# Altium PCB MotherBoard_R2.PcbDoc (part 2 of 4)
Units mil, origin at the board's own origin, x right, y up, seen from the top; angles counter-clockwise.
Board outline 9500 x 4600 mil, 4 copper layers (Top Layer, Power Layer, GND Layer, Bottom Layer), stack 61.6 mil thick; 206 components, 289 nets, 935 pads, 328 vias.
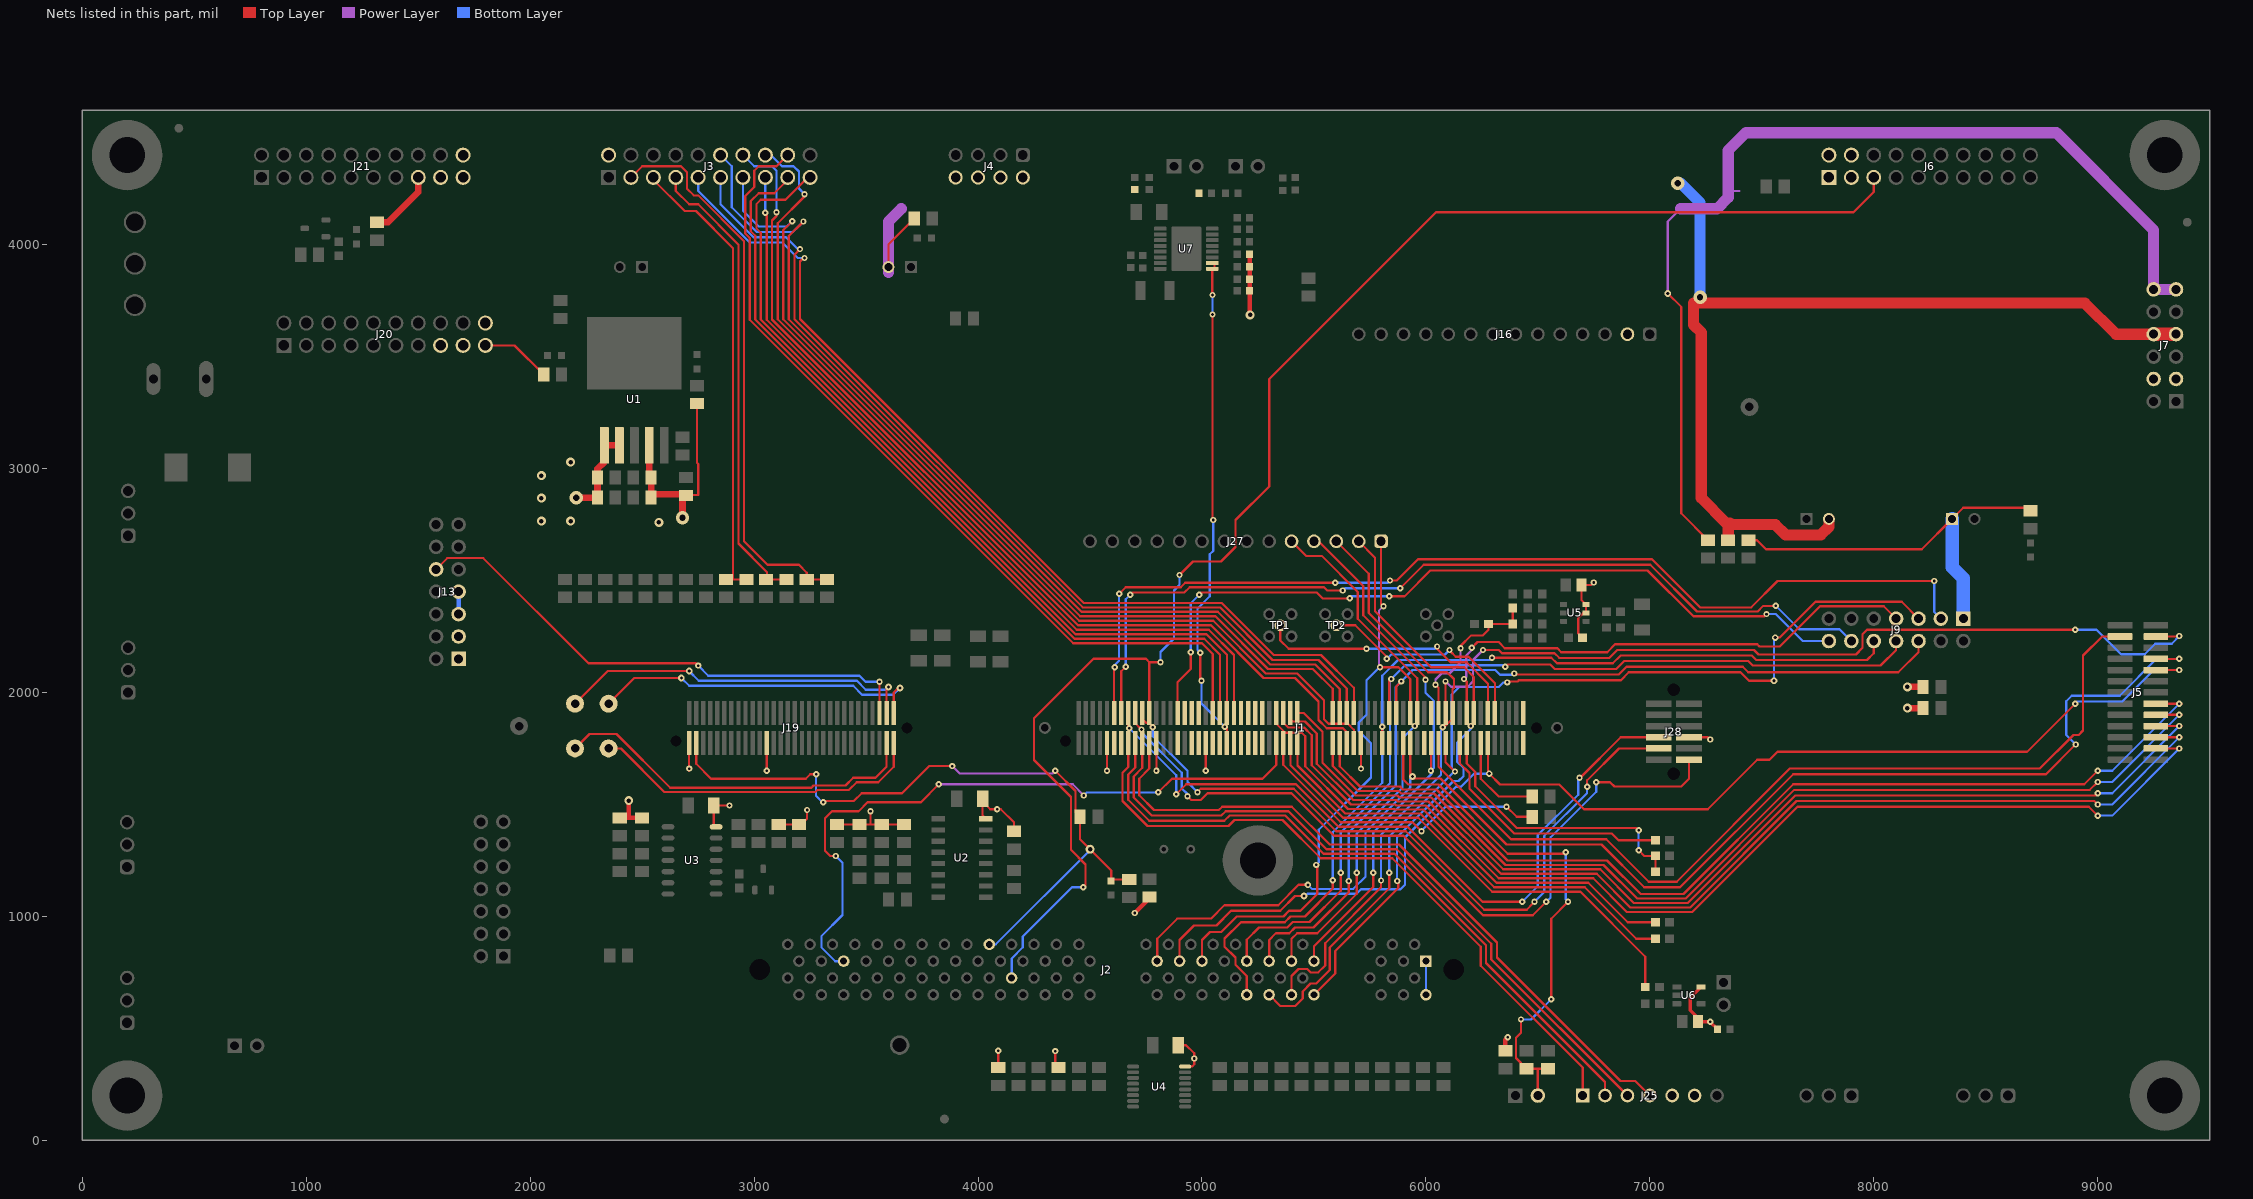
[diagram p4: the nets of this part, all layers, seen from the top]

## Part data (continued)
FID1 FID2 FID3: library part CMP-0077181-1, "Fiducial mark.  There is nothing to buy or mount.", Manufacturer=N/A
GP1 GP2 TP7 TP8 TP9 TP10: library part CMP-0078143-3, "TEST POINT.  No entry in BOM.", Manufacturer=N/A
H1 H2 H3 H4 H5: library part CMP-0003617-1, "Machine Screw, Round, #4-40 x 1/4, Nylon, Philips panhead", Manufacturer="B&F Fastener Supply", Supplier Part Number 1=H542-ND
J1: library part CMP-0003814-2, "C2000 controlCARD-120HSEC connector, SMT", Manufacturer=Samtec
J2: library part CMP-0075002-1, "Connector, DIM 1.27 mm 100 CKTS, An Identical Molex SD-87630-001  obsolete", Manufacturer="Texas Instruments"
J3 J6: library part CMP-0054719-2, "Header (Shrouded), 2.54mm, 10x2, Gold, TH", Color=Black, Current_A=3A, Manufacturer="Sullins Connector Solutions", Supplier Part Number 1=S9180-ND, Voltage_V=1kV
J4: library part CMP-0054803-2, "Header, 2.54mm, 4x2, Gold, R/A, TH", Color=Black, Current_A=3A, Manufacturer="Wurth Elektronik", Supplier Part Number 1=732-5353-ND, Voltage_V=250V
J5: library part CMP-0089180-1, Current_A=3.4A, Digikey Part Number=SAM9460-ND, Manufacturer=Samtec, Mouser Part Number=200-FTSH11301FDVK, Operating Temperature Range="-55°C to +125°C"
J7: library part CMP-0075412-2, "Header, 100mil, 6x2, Gold, TH", Color=Black, Current_A=6.3A, Manufacturer=Samtec, Supplier Part Number 1=SAM1028-06-ND, Voltage_V=550V
J8 J10 J12 J17 J23 J26: library part CMP-0054796-2, "Header, 2.54 mm, 3x1, Gold, TH", Color=Black, Manufacturer="Wurth Elektronik", Supplier Part Number 1=732-5316-ND
J9 J13 J22: library part CMP-0054695-2, "Header (shrouded), 100 mil, 7x2, Gold, TH", Manufacturer="Sullins Connector Solutions", Supplier Part Number 1=S9170-ND
J11 J15 J18 J24 J34: library part CMP-0054566-1, "Header, 100mil, 2x1, Gold, TH", Color=Black, Current_A=3A, Manufacturer="Sullins Connector Solutions", Supplier Part Number 1=S1011E-02-ND, Voltage_V=1.8kV
J14: library part CMP-0075114-1, "Power Jack, 2mm, R/A, TH", Color=Black, Manufacturer="CUI Inc.", Supplier Part Number 1=CP-037AH-ND
J16 J27: library part CMP-0055711-1, "Receptacle, 2.54mm, 14x1, Gold, TH", Color=Black, Current_A=4.7A, Manufacturer=Samtec, Supplier Part Number 1=SAM1209-14-ND, Voltage_V=465V
J19: library part CMP-0003859-2, "C2000 controlCARD-180HSEC (60-pin addon) connector, SMT", Manufacturer=Samtec
J20 J21: library part CMP-0054720-2, "Header (Shrouded), 2.54mm, 10x2, Gold, Black, TH", Color=Black, Current_A=3A, Manufacturer="Sullins Connector Solutions", Supplier Part Number 1=S9172-ND, Voltage_V=1kV
J25: library part CMP-0054674-1, "Receptacle, 2.54mm, 7x1, Gold, TH", Color=Black, Current_A=3A, Manufacturer="Sullins Connector Solutions", Supplier Part Number 1=S7040-ND, Voltage_V=250V
J28: library part CMP-0075601-1, "Header(Shrouded), 1.27mm, 6x2, Tin, SMT", Color=Black, Current_A=3.2A, Manufacturer=Samtec, Voltage_V=250V
J29 J30 J31 J32: library part CMP-0054836-1, "Connector, Receptacle, 100mil, 2x1, Gold plated, TH", Manufacturer="TE Connectivity", Supplier Part Number 1=A32932-ND
J33 TP1 TP2: library part CMP-0055255-1, "MMCX JACK, 50 Ohm, Gold, TH", Color=Gold, Manufacturer=Molex, Supplier Part Number 1=WM5557-ND
Logo2: library part CMP-0074844-1
Logo3: library part CMP-0074847-1, "FCC_disclaimer"
Logo4: library part CMP-0074769-1
Logo5: library part CMP-0074836-1, "IEC 61010-1 Caution Warning"
Q1 Q2: library part CMP-0000613-1, "MOSFET, N-CH, 30 V, 4 A, AEC-Q101, SOT-23", Alternate Manufacturer=None, Manufacturer="Diodes Inc.", Supplier Part Number 1=DMN3053L-7DICT-ND, Value1=0, Value2="7.3 nC"
R1 R2: library part CMP-0021991-4, "RES, 100, 1%, 0.1 W, AEC-Q200 Grade 0, 0603", Manufacturer=Vishay-Dale, Power_W=100mW, Supplier Part Number 1=541-100HCT-ND, TempCo="100 ppm/C", Tolerance_%=1%, Value2=0.1W, Value_Code=100R, ValueDisplayed=100
R3 R57 R64: library part CMP-0022895-5, "RES, 1.00 k, 1%, 0.1 W, 0603", Manufacturer=Yageo, Power_W=100mW, Supplier Part Number 1=311-1.00KHRCT-ND, TempCo="100 ppm/C", Tolerance_%=1%, Value2=0.1W, Value_Code=1k00, ValueDisplayed=1.00k
R4 R5 R6 R7 R8 R9 R10 R11 R12 R13 R14 R15 R16 R17 R18 R19 R22 R24 R25 R26 R27 R28 R32 R33 R35 R36 R54 R55 R67 R68 R69 R70 R79 R80: library part CMP-0020616-3, "RES, 0, 5%, 0.125 W, AEC-Q200 Grade 0, 0805", Manufacturer=Panasonic, Power_W=125mW, Supplier Part Number 1=P0.0ACT-ND, TempCo="600 ppm/C", Tolerance_%=5%, Value2=0.125W, Value_Code=0000, ValueDisplayed=0
R20 R21 R85 R86: library part CMP-0018760-1, "RES, 0, 5%, 0.25 W, AEC-Q200 Grade 0, 1206", Manufacturer=Vishay-Dale, Power_W=250mW, Supplier Part Number 1=541-2239-1-ND, TempCo=ppm/C, Tolerance_%=5%, Value2=0.25W, Value_Code=0000, ValueDisplayed=0
R23 R47 R48 R49 R50 R51 R52 R53 R103: library part CMP-0021848-2, "RES, 1.00 k, 1%, 0.25 W, 0805", Manufacturer=Panasonic, Power_W=250mW, Supplier Part Number 1=P16058CT-ND, TempCo="100 ppm/C", Tolerance_%=1%, Value2=0.25W, Value_Code=1k00, ValueDisplayed=1.00k
R29 R30 R34: library part CMP-0019441-2, "RES, 100 k, 0.1%, 0.125 W, 0805", Manufacturer="Yageo America", Power_W=125mW, TempCo="25 ppm/C", Tolerance_%=0.1%, Value2=0.125W, Value_Code=100k
R31 R44 R45: library part CMP-0020671-1, "RES, 20 k, 5%, 0.125 W, 0805", Manufacturer=Panasonic, Power_W=125mW, Supplier Part Number 1=P20KACT-ND, TempCo="200 ppm/C", Tolerance_%=5%, Value2=0.125W, Value_Code=20k0, ValueDisplayed=20k
R37: library part CMP-0021591-3, "RES, 1.69 k, 1%, 0.125 W, AEC-Q200 Grade 0, 0805", Manufacturer=Panasonic, Power_W=125mW, Supplier Part Number 1=P1.69KCCT-ND, TempCo="100 ppm/C", Tolerance_%=1%, Value2=0.125W, Value_Code=1k69, ValueDisplayed=1.69k
R38: library part CMP-0019324-1, "RES, 5.60 k, 0.5%, 0.1 W, 0805", Manufacturer="Susumu Co Ltd", Power_W=100mW, Supplier Part Number 1=RR12P5.6KDCT-ND, TempCo="25 ppm/C", Tolerance_%=0.5%, Value2=0.1W, Value_Code=5k60, ValueDisplayed=5.60k
R39 R46: library part CMP-0019268-2, "RES, 3.74 k, 0.5%, 0.1 W, 0805", Manufacturer="Susumu Co Ltd", Power_W=100mW, Supplier Part Number 1=RR12P3.74KDCT-ND, TempCo="25 ppm/C", Tolerance_%=0.5%, Value2=0.1W, Value_Code=3k74, ValueDisplayed=3.74k
R40 R43: library part CMP-0021809-3, "RES, 9.09 k, 1%, 0.125 W, AEC-Q200 Grade 0, 0805", Manufacturer=Panasonic, Power_W=125mW, Supplier Part Number 1=P9.09KCCT-ND, TempCo="100 ppm/C", Tolerance_%=1%, Value2=0.125W, Value_Code=9k09, ValueDisplayed=9.09k
R41: library part CMP-0021761-3, "RES, 6.19 k, 1%, 0.125 W, AEC-Q200 Grade 0, 0805", Manufacturer=Panasonic, Power_W=125mW, Supplier Part Number 1=P6.19KCCT-ND, TempCo="100 ppm/C", Tolerance_%=1%, Value2=0.125W, Value_Code=6k19, ValueDisplayed=6.19k
R42: library part CMP-0019292-2, "RES, 4.53 k, 0.5%, 0.1 W, 0805", Manufacturer="Susumu Co Ltd", Power_W=100mW, Supplier Part Number 1=RR12P4.53KDCT-ND, TempCo="25 ppm/C", Tolerance_%=0.5%, Value2=0.1W, Value_Code=4k53, ValueDisplayed=4.53k
R56 R58 R59 R63 R65 R71 R72: library part CMP-0081973-1, "RES, 0, 0%, 0.25 W, AEC-Q200 Grade 0, 0603", Manufacturer=Vishay-Dale, Power_W=250mW, Supplier Part Number 1=541-2779-1-ND, Tolerance_%=0%, Value2=0.25W, Value_Code=0
R60: library part CMP-0022004-4, "RES, 10.0, 1%, 0.25 W, AEC-Q200 Grade 0, 0603", Manufacturer=Vishay-Dale, Power_W=250mW, Supplier Part Number 1=541-10.0SCT-ND, TempCo="100 ppm/C", Tolerance_%=1%, Value2=0.25W, Value_Code=10R0, ValueDisplayed=10.0
R61: library part CMP-0017094-3, "RES, 5.36, 1%, 0.25 W, AEC-Q200 Grade 0, 1206", Manufacturer=Vishay-Dale, Power_W=250mW, Supplier Part Number 1=541-5.36FFCT-ND, TempCo="100 ppm/C", Tolerance_%=1%, Value2=0.25W, Value_Code=5R36, ValueDisplayed=5.36
R62: library part CMP-0022692-3, "RES, 22.0 k, 1%, 0.1 W, AEC-Q200 Grade 0, 0603", Manufacturer=Panasonic, Power_W=100mW, Supplier Part Number 1=P22.0KHCT-ND, TempCo="100 ppm/C", Tolerance_%=1%, Value2=0.1W, Value_Code=22k0, ValueDisplayed=22.0k
R66: library part CMP-0022865-5, "RES, 1.05 k, 1%, 0.1 W, 0603", Manufacturer=Yageo, Power_W=100mW, Supplier Part Number 1=311-1.05KHRCT-ND, TempCo="100 ppm/C", Tolerance_%=1%, Value2=0.1W, Value_Code=1k05, ValueDisplayed=1.05k
R73: library part CMP-0021547-3, "RES, 12.1 k, 1%, 0.125 W, AEC-Q200 Grade 0, 0805", Manufacturer=Panasonic, Power_W=125mW, Supplier Part Number 1=P12.1KCCT-ND, TempCo="100 ppm/C", Tolerance_%=1%, Value2=0.125W, Value_Code=12k1, ValueDisplayed=12.1k
R74 R75: library part CMP-0021733-3, "RES, 4.99 k, 1%, 0.125 W, AEC-Q200 Grade 0, 0805", Manufacturer=Panasonic, Power_W=125mW, Supplier Part Number 1=P4.99KCCT-ND, TempCo="100 ppm/C", Tolerance_%=1%, Value2=0.125W, Value_Code=4k99, ValueDisplayed=4.99k
R76 R78: library part CMP-0021683-3, "RES, 3.40 k, 1%, 0.125 W, AEC-Q200 Grade 0, 0805", Manufacturer=Panasonic, Power_W=125mW, Supplier Part Number 1=P3.40KCCT-ND, TempCo="100 ppm/C", Tolerance_%=1%, Value2=0.125W, Value_Code=3k40, ValueDisplayed=3.40k
R77 R101: library part CMP-0020909-2, "RES, 15.0 k, 1%, 0.125 W, 0805", Manufacturer=Vishay-Dale, Power_W=125mW, Supplier Part Number 1=541-15.0KCCT-ND, TempCo="100 ppm/C", Tolerance_%=1%, Value2=0.125W, Value_Code=15k0, ValueDisplayed=15.0k
R81 R82: library part CMP-0019095-2, "RES, 10.0 k, 0.5%, 0.1 W, 0805", Manufacturer="Susumu Co Ltd", Power_W=100mW, Supplier Part Number 1=RR12P10.0KDCT-ND, TempCo="25 ppm/C", Tolerance_%=0.5%, Value2=0.1W, Value_Code=10k0, ValueDisplayed=10.0k
R83: library part CMP-0023143-5, "RES, 49.9, 1%, 0.1 W, 0603", Manufacturer=Yageo, Power_W=100mW, Supplier Part Number 1=311-49.9HRCT-ND, TempCo="100 ppm/C", Tolerance_%=1%, Value2=0.1W, Value_Code=49R9, ValueDisplayed=49.9
R84 R87 R88 R89 R90 R93: library part CMP-0086251-1, "RES, 10.0 k, 0.05%, 0.1 W, AEC-Q200 Grade 0, 0603", Manufacturer=Panasonic, Power_W=100mW, TempCo="10 ppm/C", Tolerance_%=0.05%, Value2=0.1W, Value_Code=10k0, ValueDisplayed=10.0k
R91: library part CMP-0025733-4, "RES, 1.5 k, 5%, 0.1 W, AEC-Q200 Grade 0, 0603", Manufacturer=Vishay-Dale, Power_W=100mW, Supplier Part Number 1=541-1.5KGCT-ND, TempCo="200 ppm/C", Tolerance_%=5%, Value2=0.1W, Value_Code=1k50, ValueDisplayed=1.5k
R92 R94 R95 R96 R97 R98 R99: library part CMP-0025874-3, "RES, 0, 5%, 0.1 W, 0603", Manufacturer=Panasonic, Power_W=100mW, Supplier Part Number 1=P0.0GCT-ND, TempCo="600 ppm/C", Tolerance_%=5%, Value2=0.1W, Value_Code=0000, ValueDisplayed=0
R100 R102: library part CMP-0020835-2, "RES, 100, 1%, 0.125 W, 0805", Manufacturer=Vishay-Dale, Power_W=125mW, Supplier Part Number 1=541-100CCT-ND, TempCo="100 ppm/C", Tolerance_%=1%, Value2=0.125W, Value_Code=100R, ValueDisplayed=100
S1: library part CMP-0002236-1, "Switch, Toggle SPDT 5A, 120V, TH", CurrentRating_mA=5kA, Manufacturer=E-Switch, Supplier Part Number 1=100SP3T1B1M3QEH-ND
TP3 TP4 TP5: library part CMP-0003719-1, "Testpoint", Manufacturer="Texas Instruments"
TP6: library part CMP-0055145-1, "Test Point, Compact, Orange, TH", Color=Orange, Manufacturer=Keystone, Supplier Part Number 1=36-5008-ND
U1: library part CMP-0036893-1, "Single Output Fast Transient Response LDO, 1.5 A, Adjustable 1.21 to 20 V Output, 2.1 to 20 V Input, 5-pin DDPAK (KTT), -40 to 125 degC, Green (RoHS & no Sb/Br)", Manufacturer="Texas Instruments"
U2: library part CMP-0088292-1, "3 Circuit IC Switch 2:1 240Ohm 16-SOIC", Digikey Part Number=CD4053BQM96Q1-ND, Manufacturer="Texas Instruments", Max Supply Voltage=20V, Min Supply Voltage=3V, Mouser Part Number=595-CD4053BQM96Q1, Nominal Supply Current=0.04-0.08uA, On State Resistance=125O, Operating Temperature Range="-40°C to +125°C"
U3: library part CMP-0052992-1, "Automotive Catalog Quad 2-Input Positive-NAND Gates, D0014A, LARGE T&R", F @ Nom Voltage(Max)(Mhz)=70, ICC @ Nom Voltage(Max)(mA)=0.02, Manufacturer="Texas Instruments", Operating Temperature Range(C)="-40 to 125", PartNumber=SN74HCS00QDRQ1, Rating=Automotive, tpd @ Nom Voltage(Max)(ns)=23, Voltage(Nom)(V)=5
U4: library part CMP-0066257-1, "Automotive Catalog Dual 4-Channel Analog Multiplexer/Demultiplexer, PW0016A (TSSOP-16)", Alternate Manufacturer="Texas Instruments"
U5: library part CMP-0040148-1, "Very Low Power, Rail to Rail Out, Negative Rail In, VFB Operational Amplifier, 2.5 to 5.5 V, -40 to 125 degC, 6-pin SOT23 (DBV6), Green (RoHS & no Sb/Br)", Manufacturer="Texas Instruments"
U6: library part CMP-0051573-2, "Automotive Catalog Single 2-Input Positive-AND Gate, DBV0005A (SOT-23-5)", F @ Nom Voltage(Max)(Mhz)=75, Generic Part Number=SN74AHC1G08-Q1, ICC @ Nom Voltage(Max)(mA)=0.01, Manufacturer="Texas Instruments", Operating Temperature Range="-40 to 125 C", Rating=Automotive, tpd @ Nom Voltage(Max)(ns)=12.3,7.9, Voltage(Nom)(V)=3.3,5
U7: library part CMP-0080455-1, "Automotive Grade H-Bridge Motor Driver With Integrated Current Sense and Regulation, PWP0016J (TSSOP-16)", Alternate Manufacturer="Texas Instruments"
ZZ1: library part CMP-0003616-3
ZZ2: library part CMP-0077236-1
ZZ3: library part CMP-0077237-1
ZZ4: library part CMP-0077238-1

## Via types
v1: diameter 28, hole 12, Top Layer to Bottom Layer, 238 vias
v2: diameter 40, hole 20, Top Layer to Bottom Layer, 21 vias
v3: diameter 30, hole 14, Top Layer to Bottom Layer, 19 vias
v4: diameter 28, hole 12, Top Layer to Bottom Layer, tented top, 16 vias
v5: diameter 22, hole 10, Top Layer to Bottom Layer, tented both sides, 12 vias
v6: diameter 60, hole 28, Top Layer to Bottom Layer, 9 vias
v7: diameter 50, hole 28, Top Layer to Bottom Layer, 5 vias
v8: diameter 32, hole 16, Top Layer to Bottom Layer, tented top, 4 vias
v9: diameter 22, hole 10, Top Layer to Bottom Layer, 3 vias
v10: diameter 30, hole 14, Top Layer to Bottom Layer, tented top, 1 vias

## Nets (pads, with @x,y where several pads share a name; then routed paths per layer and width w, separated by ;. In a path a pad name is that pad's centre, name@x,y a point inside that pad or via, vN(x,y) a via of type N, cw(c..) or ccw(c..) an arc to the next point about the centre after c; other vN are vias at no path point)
3V3: C3.2 C4.1 C5.1 C6.2 C7.1 C16.1 C19.1 J3.2 J6.1 J6.2 J6.3 J6.4 J13.5 J13.7 J16.2 J25.6 J28.8 R22.2 R24.2 R25.2 R29.2 R30.2 R32.2 R33.2 R34.2 R37.1 R44.2 R46.2 R62.2 R76.2 R78.2 R80.1 R84.2 R87.1 R88.2 R89.1 R93.1 R100.2 U1.4 U2.16 U3.14 U4.16 U5.5 U5.6 U6.5 | length 3736.3
  Top Layer w10: R37.1@2695,2880 2696.75,2881.75 2750,2881.75 2750,3020.78 2745,3025.78 R76.2@2745,3290 ; U3.14@2830,1400 2820,1410 C6.2@2820,1495 v1(2890,1495) ; R29.2@3110,1410 R30.2@3200,1410 3210,1410 3236.5,1436.5 v1(3236.5,1475) ; R34.2@3370,1410 R22.2@3470,1410 3520,1410 ; v1(3520,1470) 3520,1410 ; R25.2@3670,1410 R24.2@3570,1410 3520,1410 ; C5.1@4020,1525 C5.1@4020,1512.93 ; U2.16@4034.3,1436 4020,1450.3 C5.1@4020,1512.93 ; R46.2@4090,324.57 v1(4090,399.41) ; R44.2@4160,1380 4160,1420 4101.62,1478.38 v1(4085,1478.38) 4054.55,1478.38 C5.1@4020,1512.93 ; C7.1@4895,425 4928.98,425 4965.38,388.6 v1(4965.38,365) 4965.38,340 4954.94,329.57 U4.16@4924.56,329.57 U4.16@4927.25,326.88 ; R62.2@6700,2245 6680,2265 6680,2331 6704,2355 U5.5@6715.2,2355 U5.6@6715.2,2392.4 6695.43,2412.17 C16.1@6695.43,2480 6739,2480 v1(6750,2491) ; J28.8@7175,1800 7260,1800 v1(7270,1790)
  Top Layer w15: U6.5@7229,684.8 7180,635.8 7180,580 7215.43,544.57 C19.1@7215.43,530 v1@7267.44,530 ; v1(7270,530) v1@7267.44,530 ; R84.2@7302.44,495 v1@7267.44,530
  Top Layer w20: R32.2@2400,1440 2440,1440 ; v2(2440,1517.3) 2440,1440 ; R33.2@2500,1440 2440,1440 ; v1(4700,1015) 4765,1080 R78.2@4765,1086 ; R88.2@5212.56,3956.03 R89.1@5212.56,3901.03 R87.1@5212.56,3846.03 R93.1@5212.56,3793.59 5212.56,3688.44 v2(5215,3686) ; R100.2@6355,400 6355,449.72 v1(6365.56,460.28)
  Top Layer w30: U1.4@2531.93,3103.58 2531.93,2968.07 C4.1@2540,2960 C3.2@2540,2870 2555,2885 2680,2885 v6(2680,2780) ; v2(8150.06,2024.67) 8150.39,2025 R80.1@8220,2025
  Bottom Layer w20: J13.5@1679.98,2350 J13.7@1679.98,2450
  other v2: 2575,2760 2050,2765 2180,2765 2050,2868.25 2050,2968.07 2180,3028.92
3V3_ISO: J2.1 J2.51 | length 150
  Bottom Layer w10: J2.51@6000,650 J2.1@6000,800
5V: C1.1 C2.1 J1.48 J1.84 J1.98 J1.112 J7.3 J7.4 J13.1 J13.3 J19.158 J19.180 J20.15 J20.17 J20.19 J20.20 J25.5 R41.2 R74.2 R79.1 U1.1 U1.2 | length 1611.9
  Top Layer w10: J20.19@1800,3550 1930,3550 R74.2@2060,3420 ; v1@2709.61,1650 J19.180@2709.61,1775 ; v1(3056.07,1650) J19.158@3056.07,1775 ; v1(4345,398.41) 4345,339.57 R41.2@4360,324.57 ; v1(4575.98,1650) J1.112@4575.98,1775 ; v1(4796.46,1650) J1.98@4796.46,1775 ; v1(5016.93,1650) J1.84@5016.93,1775 ; v1(5709.84,1660) J1.48@5709.84,1775
  Top Layer w30: v6(2205,2870) C2.1@2300,2870 C1.1@2300,2960 2300,2999 2331.14,3030.14 U1.1@2331.14,3103.58 U1.2@2398.07,3103.58 ; v2(8150.39,1930) R79.1@8220,1930
  other v1: 2709.61,1660
5V_IPS: J4.2 J4.4 J4.6 J4.8 J7.7 J7.8 J21.15 J21.17 J21.19 J21.20 J31.2 R42.2 R75.2 R94.1 R95.1 | length 4735.8
  Top Layer w30: R75.2@1315,4100 1365,4100 1500,4235 J21.15@1500,4300
  Top Layer w50: R42.2@7350,2680 7350,2750 ; J31.2@7800,2775 7800,2740 7763,2703 7607,2703 7560,2750 7350,2750 ; J7.8@9250,3600 9082,3600 8942,3740 7195,3740 7195,3642.13 7230,3607.13 7230,2868.31 7341.18,2757.13 7357.13,2757.13 7350,2750
  Top Layer w60: J7.8@9250,3600 J7.7@9350,3600
  Bottom Layer w50: v6(7125,4274.52) 7137.02,4274.52 7224.29,4187.25 v6(7224.29,3765)
12V: J7.11 J7.12 J29.2 R43.2 R73.2 | length 5122.7
  Top Layer w10: J29.2@3600,3900 3600,4001.75 R73.2@3715,4116.75 ; v3(7080,3782) 7140,3722 7140,2800 R43.2@7260,2680
  Power Layer w10: v3(7080,3782) 7080,4103.25 7136.75,4160 ; 7350,4240 7400,4240
  Power Layer w50: J29.2@3600,3875 J29.2@3600,3900 3600,4103.39 3656.61,4160 ; 7136.75,4160 7299.19,4160 7350,4210.81 7350,4240 7350,4420 7430,4500 8815,4500 9250,4065 J7.12@9250,3800 J7.11@9350,3800
15V: J9.1 J32.1 R40.2 R77.2 | length 1825.1
  Top Layer w10: R40.2@7440,2680 7478.84,2680 7518.83,2640.01 8215,2640.01 J32.1@8350,2775 8400.24,2825.24 8686.08,2825.24 R77.2@8700,2811.32
  Bottom Layer w60: J32.1@8350,2775 8350,2560 8400,2510 J9.1@8400,2329.7
ASC_EN: J3.3 R14.2 R15.1 | length 2505.2
  Top Layer w10: J3.3@2450,4300 2500,4350 2672.97,4350 2700,4322.97 2700,4250 2730,4220 2750,4220 2955,4015 2955,2675 3060,2570 3200,2570 3235,2535 R14.2@3235,2505 R15.1@3325,2505
ASC_H: J3.5 R16.2 R17.1 | length 2061.3
  Top Layer w10: J3.5@2550,4300 2550,4290 2690,4150 2740,4150 2905,3985 R16.2@2905,2505 ; R16.2@2875,2505 R16.2@2905,2505 ; R17.1@2965,2505 R16.2@2905,2505
ASC_L: J3.7 R18.2 R19.1 | length 2074.7
  Top Layer w10: J3.7@2650,4300 2650,4240 2710,4180 2750,4180 2930,4000 2930,2665 3057.6,2537.4 3057.6,2505 R19.1@3145,2505
C2K_ADC-A0: J1.9 TP2.1 | length 1002.5
  Top Layer w10: TP2.1@5600,2300 5685,2300 5830,2155 v1(5825,2150) ; v1@6110,2195 6110,2182.8 6132.8,2160 6190,2160 6308.27,2041.73 J1.9@6308.27,1908.86
  Bottom Layer w10: v1(5825,2150) 5825.47,2150 5845.55,2170.08 6085.08,2170.08 v1(6105,2190) v1@6110,2195
C2K_ADC-A1: J1.11 TP1.1 | length 1219.7
  Top Layer w10: TP1.1@5350,2300 5350,2232.09 5387.09,2195 v1(5735,2195) ; v1(6050,2205) 6050,2195 6110,2135 6182.01,2135 6276.77,2040.24 J1.11@6276.77,1908.86
  Bottom Layer w10: v1(5735,2195) 6040,2195 v1(6050,2205)
C2K_ADC-A2: J1.15 J2.57 J27.2 | length 2664.8
  Top Layer w10: J2.57@5500,650 5595,745 5595,845.46 5876.62,1127.07 v1@5876.62,1160 ; J27.2@5700,2675 5772.83,2602.17 5772.83,2362.17 6022.67,2112.33 6170.98,2112.33 6213.78,2069.53 J1.15@6213.78,1908.86 6213.78,1858.78 6205,1850 v1(6200.37,1850)
  Bottom Layer w10: v1@5876.62,1160 5871.05,1165.57 5871.05,1353.11 6122.94,1605 6146,1605 6168.47,1627.47 6168.47,1661.16 6140,1689.63 6140,1776.53 6200.37,1836.91 v1(6200.37,1850)
  other v1: 5871.62,1158
C2K_ADC-A3: J1.17 J9.7 | length 2350.8
  Top Layer w10: v1(6170,2060) 6182.28,2047.72 J1.17@6182.28,1908.86 ; v1(6205,2200) 6230,2225 6325,2225 6352.5,2197.5 6587.5,2197.5 6605,2180 6810,2180 6845,2215 7480,2215 7490,2205 7580,2205 7760,2385 8044.7,2385 J9.7@8100,2329.7
  Power Layer w10: v1(6170,2060) 6180,2070 6180,2165 6205,2190 v1(6205,2200)
C2K_ADC-A4: J1.21 J2.59 J27.3 | length 2665.2
  Top Layer w10: J2.59@5400,650 5400,733.62 5431.38,765 5470,765 5485,750 5519.41,750 5550,780.59 5550,880 5800,1130 v1(5800,1160) ; J27.3@5600,2675 5745,2530 5745,2355 6010,2090 6094.75,2090 6125,2059.75 6125,2019.7 6119.29,2013.99 J1.21@6119.29,1908.86 6119.29,1882.45 v1@6081.84,1845
  Bottom Layer w10: v1(5800,1160) 5800,1364.63 6067.75,1632.37 6067.75,1830.91 v1@6081.84,1845
  other v1: 6075,1845
C2K_ADC-A5: J1.23 J5.4 | length 3855.5
  Top Layer w10: J1.23@6087.8,1908.86 v1(6087.8,2049.44) ; v1(6255,2190) 6325,2190 6340,2175 6574.53,2175 6595,2154.53 6819.53,2154.53 6855,2190 7465,2190 7485,2170 7920.44,2170 7950,2199.56 7950,2260 7970,2280 v1(8900,2280) ; J5.4@9260.24,2250 9363.15,2250 v1(9365,2251.85)
  Power Layer w10: v1(6087.8,2049.44) 6111.85,2025.39 6186.86,2025.39 6210,2048.53 6210,2145 v1(6255,2190)
  Bottom Layer w10: v1(8900,2280) 8995,2280 9104.32,2170.68 9210.29,2170.68 9257.18,2217.57 9330.72,2217.57 v1(9365,2251.85)
C2K_ADC-B0: J1.12 J2.19 J5.10 | length 5559
  Top Layer w10: J2.19@4900,800 4900,895 4964.5,959.5 5064.5,959.5 5130,1025 5350,1025 5415.58,1090.58 v3(5455.29,1090.58) ; J1.12@6276.77,1775 6276.77,1643.62 v3(6282.99,1637.4) 6331.28,1589.11 6595.89,1589.11 6706,1479 7259,1479 7480,1700 7535,1700 7570,1735 8685,1735 v1(8900,1950) ; J5.10@9260.24,2100 v1(9365,2100)
  Bottom Layer w10: v3(5455.29,1090.58) 5460.58,1090.58 5470.68,1100.68 5690.23,1100.68 5710.23,1120.68 5886.93,1120.68 5907.03,1140.78 5907.03,1352.03 6134,1579 6156.28,1579 6214.69,1637.4 v3(6282.99,1637.4) ; v1(8900,1950) 8910,1960 9110.36,1960 9250.37,2100 v1(9365,2100)
C2K_ADC-B1: J1.14 R5.1 | length 422.8
  Top Layer w10: J1.14@6245.28,1775 6245.28,1614.72 6325,1535 R5.1@6474.76,1535
C2K_ADC-B2: J1.18 R56.2 R59.2 | length 1266.1
  Top Layer w10: J1.18@6182.28,1775 6182.28,1682.72 6220,1645 6220,1581.1 6406.1,1395 6940,1395 v1(6950,1385) ; v1(6950,1295) 6975,1270 R56.2@7025,1270 R59.2@7025,1200
  Bottom Layer w10: v1(6950,1295) v1(6950,1385)
C2K_ADC-B3: J1.20 R58.2 | length 1148.6
  Top Layer w10: J1.20@6150.79,1775 6150.79,1684.49 6195,1640.28 6195,1570 6395,1370 6830,1370 6860,1340 R58.2@7025,1340
C2K_ADC-B4: J1.24 J2.61 J9.5 | length 4432.5
  Top Layer w10: J2.61@5300,650 5350,600 5416.38,600 5450,633.62 5450,665 5485,700 5510,700 5570.9,760.9 5570.9,861.03 5835.87,1126 v1(5835.87,1195) ; J1.24@6087.8,1775 6087.8,1688.74 6129.28,1647.25 v1(6130,1647.25) v1@6133.22,1647.25 ; v1(6362.82,2045) 6367.27,2049.44 6409.44,2049.44 6415,2055 6871.15,2055 6906.15,2090 7405,2090 7442.8,2052.2 v3(7555,2052.2) v3@7563.19,2052.2 ; v3(7560,2245) 7580,2245 7740,2405 8124.7,2405 J9.5@8200,2329.7
  Bottom Layer w10: v1(5835.87,1195) 5835.87,1355.19 5835.46,1355.61 6127.1,1647.25 v1(6130,1647.25) 6115,1662.25 6115,1990.7 6148.97,2024.67 6325,2024.67 6345.33,2045 v1(6362.82,2045) ; v3(7555,2052.2) 7555,2240 v3(7560,2245)
C2K_ADC-B5: J1.26 J5.3 | length 4012.6
  Top Layer w10: J1.26@6056.3,1775 6056.3,1668.7 6380,1345 6805,1345 6995,1155 7120,1155 7625,1660 8741.99,1660 8891.99,1810 8915,1810 8935,1830 8935,2165 9020,2250 J5.3@9100,2250
C2K_ADC-C2: J1.31 J2.9 J27.5 | length 2434.1
  Top Layer w10: J2.9@5400,800 5400,900 5425,925 5515,925 5690.68,1100.68 v1(5690.68,1195) ; J27.5@5400,2675 5465,2610 5535,2610 5696,2449 5696,2329 5961.81,2063.19 J1.31@5961.81,1908.86 5961.81,1864.29 5950,1852.48 v1(5950,1850)
  Bottom Layer w10: v1(5690.68,1195) 5690.68,1369.81 5895,1574.13 5895,1795 v1(5950,1850)
C2K_ADC-C3: J1.33 J2.17 J27.1 | length 2758.6
  Top Layer w10: J2.17@5000,800 5000,894.49 5035.51,930 5085.75,930 5155.75,1000 5363.85,1000 5388.85,1025 5440,1025 5515,1100 5515,1225 v1(5510,1230) ; v1(5795,2112.33) 5877.67,2112.33 5930.31,2059.68 J1.33@5930.31,1908.86 ; J27.1@5800,2675 5800,2395.37 v1(5810.37,2385)
  Power Layer w10: v1(5795,2112.33) 5790,2117.33 5790,2364.63 v1(5810.37,2385)
  Bottom Layer w10: v1(5510,1230) 5521.72,1241.72 5521.72,1387.41 5754.88,1620.57 5754.88,1773.57 5700,1828.45 5700,1865.53 5735,1900.53 5735,2054.64 v1@5793.85,2113.49
C2K_ADC-C4: J1.37 J2.11 J9.6 | length 4191.1
  Top Layer w10: J2.11@5300,800 5300,895 5330,925 5390,925 5415,950 5498,950 5655,1107 v1(5655,1158) ; J1.37@5867.32,1908.86 5867.32,2026.77 v1(5890,2049.44) ; v1(6395,2085) 6395,2083.19 6391.81,2080 6860.83,2080 6895.83,2115 7415,2115 7440,2090 8110,2090 8200,2180 J9.6@8200,2229.7
  Bottom Layer w10: v1(5655,1158) 5655,1375 5690,1410 5865,1585 5865,2024.44 v1(5890,2049.44) 5940.56,2100 6310,2100 6331.08,2078.92 6388.92,2078.92 v1(6395,2085)
C2K_ADC-C5: J1.39 J2.13 J9.8 | length 4188
  Top Layer w10: J2.13@5200,800 5200,895.59 5254.41,950 5380.67,950 5405.67,975 5480,975 5620,1115 v1(5620,1195) ; J1.39@5835.83,1908.86 5835.83,2050.83 v1(5845,2060) ; v1(6354.76,2115) 6365,2125.24 6554.76,2125.24 6575,2105 6850,2105 6885.83,2140.83 7439.17,2140.83 7460,2120 8030,2120 8100,2190 J9.8@8100,2229.7
  Bottom Layer w10: v1(5620,1195) 5620,1374.84 5839.82,1594.66 5839.82,2054.82 v1(5845,2060) 5907,2122 6347.76,2122 v1(6354.76,2115)
C2K_ADC-D0: J1.28 J2.7 J27.4 | length 2461.1
  Top Layer w10: J2.7@5500,800 5500,866.37 5764.54,1130.92 v1(5764.54,1195) ; J27.4@5500,2675 5520,2675 5720,2475 5720,2345 6001.75,2063.25 5998.31,2059.81 v1(5998.31,2057.41) ; v1(6022.35,1650) 6022.35,1772.15 6025,1774.8 J1.28@6024.8,1775
  Bottom Layer w10: v1(5764.54,1195) 5764.54,1375.15 6025,1635.61 6022.35,1638.26 v1(6022.35,1650) 6035,1662.65 6035,1962.45 6001.75,1995.7 5998.31,1999.14 v1(5998.31,2057.41)
C2K_ADC-D1: J1.30
C2K_ADC-D2: J1.34 J2.21 J5.8 | length 6203.4
  Top Layer w10: J2.21@4800,800 4800,900 4890,990 5040,990 5100,1050 5340.37,1050 5431.15,1140.78 v3(5472.92,1140.78) ; J1.34@5930.31,1775 5930.31,1620.32 5935,1625 v3(5940,1625) 5940,1622 5934,1616 6064.79,1616 6360.2,1320.59 6784.41,1320.59 6975,1130 7135,1130 7640,1635 8769,1635 8900,1766 v1@8900,1768 ; J5.8@9260.24,2150 v1(9365,2150)
  Bottom Layer w10: v3(5472.92,1140.78) 5490.82,1122.87 5675.3,1122.87 5730,1177.57 5730,1375.33 5930,1575.33 5930,1615 v3(5940,1625) ; v1(8902,1768) 8860,1810 8860,1961.25 8884.13,1985.38 9098.25,1985.38 9262.87,2150 v1(9365,2150)
C2K_ADC-D3: C24.2 J1.36 J18.2 R102.2 | length 2356.5
  Top Layer w10: J1.36@5898.82,1775 5898.82,1611.18 5920.75,1589.25 6056.31,1589.25 6365.56,1280 6618.57,1280 v1(6624.57,1286) ; v1(6425,540) 6425,480.58 6402.76,458.34 6402.76,367.24 R102.2@6450,320 6500,320 ; J18.2@6500,200 6500,320 ; C24.2@6545,320 6500,320 ; v1(6560,630.24) 6560,990 v1(6635,1065)
  Bottom Layer w10: v1(6425,540) 6469.76,540 v1(6560,630.24) ; v1(6624.57,1286) 6624.57,1075.43 v1(6635,1065)
C2K_ADC-D4: J1.40
C2K_ADC-D5: J1.42 J2.63 J9.10 | length 4347.5
  Top Layer w10: J2.63@5200,650 5200,734 5150,784 5150,816 5101,865 5101,901 5174,974 5369.69,974 5395.69,1000 5460,1000 5584.16,1124.16 v1(5584.16,1160.84) ; J1.42@5804.33,1775 5805,1775.67 v1(5805,1847.09) ; v1(6295,2155) 6560,2155 6585,2130 6835,2130 6870,2165 7455,2165 7475,2145 7970,2145 8000,2175 J9.10@8000,2229.7
  Bottom Layer w10: v1@5578.33,1155 v1(5584.16,1160.84) 5584.16,1376.29 5805,1597.13 v1(5805,1847.09) 5805,2075 5875,2145 6285,2145 v1(6295,2155) ; v1(6295,2155) 6303.36,2155 6295,2146.64 v1(6295,2155)
C2K_ADCIN14: C17.1 J1.25 R60.2 R83.1 | length 732.5
  Top Layer w10: v1(6042.64,2035) 6056.3,2021.34 J1.25@6056.3,1908.86 ; v1(6155,2197.5) 6155,2207.13 6202.87,2255 6255,2255 6280,2280 R83.1@6280,2306 C17.1@6388.23,2306 R60.2@6388.23,2377.4
  Power Layer w10: v1(6042.64,2035) 6042.64,2058.32 6069.32,2085 6105.58,2085 6155,2134.42 v1(6155,2197.5)
C2K_ADCIN15: J1.27
C2K_EMU0: J1.2
C2K_EMU1: J1.1
C2K_ERRSTS: D6.1 J2.32 J19.178 R101.1 R103.1 TP5.1 | length 3239.2
  Top Layer w10: J19.178@2741.11,1775 2741.11,1681.2 2807.31,1615 3230,1615 3249.97,1634.97 v4(3276.78,1634.97) ; v1(3308.04,1510) 3313.04,1515 3445,1515 3480,1550 3660.75,1550 3781.96,1671.21 v1(3885,1671.21) ; v1(4345,1650) 4435,1560 4435,1465 R103.1@4455,1445 4455,1345 TP5.1@4500,1300 4594.67,1205.33 D6.1@4594.67,1158.5 4600,1163.83 4601.17,1165 R101.1@4675,1165
  Power Layer w10: v1(3885,1671.21) 3917.75,1638.46 4333.46,1638.46 v1(4345,1650)
  Bottom Layer w10: v4(3276.78,1634.97) 3276.78,1537.68 3304.46,1510 v1(3308.04,1510) ; J2.32@4050,875 4079,875 4504,1300 TP5.1@4500,1300
C2K_GPIO0: J1.49 J3.9 | length 4210.3
  Top Layer w10: v1(3225,3940) 3220,3940 3205,3925 3205,3667.5 4472.5,2400 5088.01,2400 5320.92,2167.09 5531.94,2167.09 5678.35,2020.68 J1.49@5678.35,1908.86
  Bottom Layer w10: J3.9@2750,4300 2750,4240 2980,4010 3124.94,4010 3194.94,3940 v1(3225,3940)
C2K_GPIO1: J1.51 J3.11 | length 4140.2
  Top Layer w10: v1(3205,3980) 3180,3955 3180,3667.22 4467.22,2380 5080,2380 5315,2145 5520,2145 5646.85,2018.15 J1.51@5646.85,1908.86
  Bottom Layer w10: J3.11@2850,4300 2850,4180 2997,4033 3142,4033 3195,3980 v1(3205,3980)
C2K_GPIO2: J1.53 J3.12 | length 4352.7
  Top Layer w10: v1(3220,4103.37) 3155,4038.37 3155,3666.94 4461.94,2360 5070,2360 5304.76,2125.24 5505.66,2125.24 5615.35,2015.55 J1.53@5615.35,1908.86
  Bottom Layer w10: J3.12@2850,4400 2900,4350 2900,4167.43 3010.43,4057 3173.63,4057 v1(3220,4103.37)
C2K_GPIO3: J1.55 J3.13 | length 4106.8
  Top Layer w10: v1(3169.61,4105) 3130,4065.39 3130,3666.67 4456.67,2340 5060,2340 5295,2105 5495,2105 5583.86,2016.14 J1.55@5583.86,1908.86
  Bottom Layer w10: J3.13@2950,4300 2950,4151.59 3020.59,4081 3145.61,4081 v1(3169.61,4105)
C2K_GPIO4: J1.50 J3.16 | length 4341.4
  Top Layer w10: v1(3225,4225.39) 3225,4215 3105,4095 3105,3666.39 4451.39,2320 5050,2320 5285,2085 5425,2085 5545,1965 5545,1880 5565,1860 5651.93,1860 5678.35,1833.58 J1.50@5678.35,1775
  Bottom Layer w10: J3.16@3050,4400 3074,4400 3124,4350 3176.25,4350 3200,4326.25 3200,4250.39 v1(3225,4225.39)
C2K_GPIO5: J1.52 J3.14 | length 4278.2
  Top Layer w10: v1(3100,4145) 3100,4128 3080,4108 3080,3666.11 4446.11,2300 5040,2300 5275,2065 5415,2065 5520,1960 5520,1876.93 5556.93,1840 5630,1840 5646.85,1823.15 J1.52@5646.85,1775
  Bottom Layer w10: J3.14@2950,4400 3000,4350 3080,4350 3100,4330 v1(3100,4145)
C2K_GPIO6: J1.54 J5.16 | length 4557.5
  Top Layer w10: J1.54@5615.35,1775 5615.35,1670.11 5705.46,1580 5884.04,1580 5896.91,1567.13 6047.64,1567.13 6364.76,1250 6809,1250 6959,1100 7150,1100 7640,1590 8940,1590 v1(9000,1650) ; J5.16@9260.24,1950 v1(9365,1950) v1@9375,1950
  Bottom Layer w10: v1(9000,1650) 9065,1650 v1(9365,1950)
C2K_GPIO7: J1.56 J5.18 | length 4583.7
  Top Layer w10: J1.56@5583.86,1775 5583.86,1672.14 5696,1560 5878.76,1560 5889.51,1549.25 6035.75,1549.25 6355,1230 6793.65,1230 6943.65,1080 7160,1080 7645,1565 8965,1565 v1(9000,1600) ; J5.18@9260.24,1900 v1(9365,1900) v1@9375,1900
  Bottom Layer w10: v1(9000,1600) 9065,1600 v1(9365,1900)
C2K_GPIO8: J1.57 J5.20 | length 4812.8
  Top Layer w10: J1.57@5426.38,1908.86 5453.14,1908.86 5538,1824 5538,1686.41 5684.41,1540 5873.48,1540 5882.11,1531.38 6023.62,1531.38 6345,1210 6778.29,1210 6928.29,1060 7169,1060 7649,1540 8990,1540 v1(9000,1550) ; J5.20@9260.24,1850 v1(9365,1850) v1@9375,1850
  Bottom Layer w10: v1(9000,1550) 9065,1550 v1(9365,1850)
C2K_GPIO9: J1.59 J5.22 | length 4867.9
  Top Layer w10: J1.59@5394.88,1908.86 5394.88,1880.12 5405,1870 5460,1870 5513,1817 5513,1682 5675,1520 5868.21,1520 5874.7,1513.5 6011.5,1513.5 6335,1190 6762.94,1190 6912.94,1040 7180,1040 7655,1515 8985,1515 v1(9000,1500) ; J5.22@9260.24,1800 v1(9365,1800) v1@9375,1800
  Bottom Layer w10: v1(9000,1500) 9065,1500 v1(9365,1800)
C2K_GPIO10: J1.61 J5.24 | length 5028.8
  Top Layer w10: J1.61@5363.39,1908.86 5363.39,1865.35 5385.67,1843.07 5455.93,1843.07 5490,1809 5490,1675 5665,1500 5862.93,1500 5867.3,1495.63 ; 5972.02,1495.63 5867.3,1495.63 ; v1(9000,1450) 8960,1490 7659.42,1490 7189.42,1020 6897.58,1020 6747.58,1170 6324.8,1170 5999.17,1495.63 5867.3,1495.63 ; J5.24@9260.24,1750 v1(9365,1750) v1@9375,1750
  Bottom Layer w10: v1(9000,1450) 9065,1450 v1(9365,1750)
C2K_GPIO11: J1.63 R65.2 | length 2187.4
  Top Layer w10: J1.63@5331.89,1908.86 5331.89,1860.2 5372.09,1820 5446,1820 5461.14,1804.86 5461.14,1670.79 5651.93,1480 5857.65,1480 5859.9,1477.76 5987.8,1477.76 6315.56,1150 6725,1150 6901,974 R65.2@7025,974
C2K_GPIO12: J1.58 R63.2 | length 2020.4
  Top Layer w10: J1.58@5426.38,1775 5426.38,1673.62 5640,1460 5852.37,1460 5852.49,1459.88 5975.12,1459.88 6305,1130 6709.41,1130 6939.41,900 R63.2@7025,900
C2K_GPIO13: J1.60 R71.1 | length 2174.4
  Top Layer w10: J1.60@5394.88,1775 5394.88,1675.12 5630,1440 5965.75,1440 6295.75,1110 6690,1110 6980,820 R71.1@6980,684.8
C2K_GPIO14: J1.62 R4.1 | length 1407.1
  Top Layer w10: J1.62@5363.39,1775 5363.39,1676.61 5620,1420 5940,1420 v1(5980,1380) ; v1(6360,1490) 6405.5,1444.5 R4.1@6475,1444.5
  Bottom Layer w10: v1(5980,1380) v1@5982.77,1380 ; v1@5985.8,1376.97 v1@5982.77,1380 ; v1(6360,1490) 6087.23,1490 5980,1382.77 v1@5982.77,1380
C2K_GPIO15: J1.64 J2.45 | length 3041.8
  Top Layer w10: v1(3365,1270) 3339.54,1270 3317,1292.54 3317,1439 3348,1470 3466.62,1470 3506.62,1510 3745,1510 v1(3825,1590) ; v1(4805,1553.86) 4866.14,1615 5270.39,1615 5331.89,1676.5 J1.64@5331.89,1775
  Power Layer w10: v1(3825,1590) 4422.5,1590 v1(4472.5,1540)
  Bottom Layer w10: v1(3365,1270) 3395,1240 3395,1006.08 3300.28,911.36 3300.28,862.43 3362.71,800 J2.45@3400,800 ; v1(4472.5,1540) 4486.36,1553.86 v1(4805,1553.86)
C2K_GPIO16: J1.67
C2K_GPIO17: J1.69
C2K_GPIO18: J1.71
C2K_GPIO19: J1.73
C2K_GPIO20: J1.68
C2K_GPIO21: J1.70
C2K_GPIO22: J1.72
C2K_GPIO23: J1.74
C2K_GPIO24: J1.75 J3.15 | length 3603.2
  Top Layer w10: v1(3050,4142) 3056.07,4135.93 3056.07,3664.76 4440.83,2280 5030,2280 5142.91,2167.09 J1.75@5142.91,1908.86
  Bottom Layer w10: v1(3050,4142) J3.15@3050,4300
C2K_GPIO25: J1.77 J3.19 | length 3773.6
  Top Layer w10: J3.19@3250,4300 3240,4300 3140,4200 3030,4200 3010,4180 3010,4072.6 3030,4052.6 3030,3665.56 4435.56,2260 5020,2260 5111.42,2168.58 J1.77@5111.42,1908.86
C2K_GPIO26: J1.79 J3.17 | length 3707.8
  Top Layer w10: J3.17@3150,4300 3150,4290 3090,4230 3020,4230 2985,4195 2985,4060 3005,4040 3005,3665.28 4430.28,2240 5010,2240 5079.92,2170.08 J1.79@5079.92,1908.86
C2K_GPIO27: J1.81 J3.18 | length 3818.6
  Top Layer w10: J3.18@3150,4400 3100,4350 3020,4350 3000,4330 3000,4257.57 2960,4217.57 2960,4050 2980,4030 2980,3665 4425,2220 5000,2220 5048.43,2171.57 J1.81@5048.43,1908.86
C2K_GPIO28: J1.76
C2K_GPIO29: J1.78 U7.1 U7.2 | length 2236.8
  Top Layer w10: v1(4992.43,2177.8) 4992.43,2057.77 v1(4998,2052.2) ; U7.1@5046.14,3892.06 5046.14,3775.75 v1(5046.89,3775) ; v1(5046.89,3688) 5046.89,2773.11 v1(5050,2770) ; U7.1@5056.14,3892.06 U7.2@5056.14,3917.65 ; v1(5101.21,1847.09) 5111.42,1836.88 J1.78@5111.42,1775
  Bottom Layer w10: v1(4992.43,2177.8) 4980,2190.23 4980,2374.25 5035,2429.25 5035,2617.21 5050,2632.21 v1(5050,2770) ; v1(4998,2052.2) 4998,1950.3 v1(5101.21,1847.09) ; v1(5046.89,3688) v1(5046.89,3775) v1@5046.89,3784.11
C2K_GPIO30: J1.80
C2K_GPIO31: J1.82
C2K_GPIO32: J1.85
C2K_GPIO33: J1.87
C2K_GPIO34: J1.86
C2K_GPIO35: J19.121 TP10.1 | length 1520.5
  Top Layer w10: TP10.1@2350,1950 2465,2065 v3(2675,2065) ; J19.121@3623,1908.86 3623,1999.54 3643.46,2020 v3(3651.61,2020)
  Bottom Layer w10: v3(2675,2065) 2710,2030 3442.09,2030 3482.09,1990 3621.61,1990 v3(3651.61,2020)
C2K_GPIO36: J19.122 TP9.1 | length 1507.6
  Top Layer w10: TP9.1@2350,1750 2405,1750 2600,1555 3272.64,1555 3282.64,1565 3424,1565 3458.32,1599.32 3554.32,1599.32 3623,1668 J19.122@3623,1775
C2K_GPIO37: J19.123 TP8.1 | length 1626.6
  Top Layer w10: TP8.1@2200,1950 2345.75,2095.75 v3(2710,2095.75) ; J19.123@3591.5,1908.86 3591.5,2016.17 v3(3600,2024.67)
  Bottom Layer w10: v3@2705,2100 v3@2709.26,2095.75 ; v3(2710,2095.75) v3@2709.26,2095.75 ; v3(3600,2024.67) 3587.93,2012.6 3498.95,2012.6 3459.36,2052.2 2752.81,2052.2 v3@2709.26,2095.75
C2K_GPIO38: J19.124 TP7.1 | length 1663.4
  Top Layer w10: TP7.1@2200,1750 2265,1815 2385,1815 2625,1575 3255.75,1575 3265,1584.25 3408.42,1584.25 3442.79,1618.62 3542.13,1618.62 3591.5,1668 J19.124@3591.5,1775
C2K_GPIO39: J1.88
C2K_GPIO40: J1.89
C2K_GPIO41: J1.91 J9.14 | length 3586.1
  Top Layer w10: J1.91@4890.94,1908.86 4890.94,2045.94 4950,2105 v1(4950,2180) ; v1(4987.93,2435.88) 4998.34,2446.29 5513.12,2446.29 5539.41,2420 5659.32,2420 v1(5660,2420.68) ; v1(5835.87,2430) 5905,2430 6020,2545 6990,2545 7195,2340 7510.75,2340 v1(7520.75,2350)
  Bottom Layer w10: v1(4950,2180) 4950,2397.95 v1(4987.93,2435.88) ; v1@5659.32,2420 v1(5660,2420.68) 5669.32,2430 v1(5835.87,2430) ; v1(7520.75,2350) 7562.8,2350 7683.1,2229.7 J9.14@7800,2229.7
C2K_GPIO45: J1.92
C2K_GPIO48: J1.99 J2.80 J6.5 | length 6979
  Top Layer w10: v1(4470,1130) 4470.75,1130 4480.12,1139.37 4480.12,1232.23 4415,1297.36 4415,1533.64 4250,1698.64 4250,1885 4515.11,2150.11 4749.86,2150.11 4764.96,2135 ; J1.99@4764.96,1908.86 J1.99@4764.96,1908.86 4765,2134.96 4764.96,2135 ; v1(4815,2135) 4764.96,2135 ; v4(4900,2525) 4960,2585 5085,2585 5150,2650 5150,2770 5300,2920 5300,3400 6045,4145 7910,4145 8000,4235 J6.5@8000,4300
  Bottom Layer w10: J2.80@4150,725 4150,811.94 4200,861.94 4200,910 4420,1130 v1(4470,1130) ; v1(4815,2135) 4815,2180.89 4875,2240.89 4875,2455.88 4900,2480.88 v4(4900,2525)
C2K_GPIO49: J1.101 J28.9 | length 3209.5
  Top Layer w10: J1.101@4733.46,1908.86 4733.46,1881.54 4750,1865 4760,1865 v1(4780,1845) ; v1(4980,1555) 4995,1570 5410,1570 5600,1380 5910,1380 6260,1030 6450,1030 v1@6477.5,1057.5 ; v1(6720,1579) 6720,1607.57 6862.43,1750 J28.9@7039.96,1750
  Bottom Layer w10: v1@4780,1835 4780,1805 4935,1650 4935,1600 v1(4980,1555) ; v1(6485,1065) 6529,1109 6529,1359.58 6720,1550.58 v1(6720,1579)
C2K_GPIO50: J1.103 J28.12 | length 3489.6
  Top Layer w10: J1.103@4701.97,1908.86 4701.97,1863.03 v1(4730,1835) ; v1(4935,1536.77) 4951.77,1520 4995,1520 5025,1550 5400,1550 5590,1360 5900,1360 6255,1005 6477.5,1005 v1(6537.5,1065) ; v1(6761,1599.32) 6822.53,1599.32 6842,1579.85 7139.85,1579.85 7175,1615 J28.12@7175,1700
  Bottom Layer w10: v1(4730,1835) 4730,1821.47 4910,1641.47 4910,1571.08 4935,1546.08 v1(4935,1536.77) ; v1(6537.5,1065) 6557,1084.5 6557,1353 6761,1557 v1(6761,1599.32)
C2K_GPIO51: J1.105 J28.7 | length 3326.5
  Top Layer w10: J1.105@4670.47,1908.86 4670.47,1844.53 v1(4675,1840) ; v1(4885,1545.37) 4929.63,1590 5420,1590 5610,1400 5918.24,1400 6253.24,1065 v1(6430,1065) ; v1(6686,1619) 6686,1616 6870,1800 J28.7@7039.96,1800
  Bottom Layer w10: v1(4675,1840) 4885,1630 v1(4885,1545.37) ; v1(6430,1065) 6500,1135 6500,1363 6680,1543 6680,1613 v1(6686,1619)
C2K_GPIO52: J1.107 J9.12 | length 3993.3
  Top Layer w10: J1.107@4638.98,1908.86 4640,1909.88 4640,2095 v1(4660,2115) ; v1(4680,2435.88) 4690.41,2446.29 4921.29,2446.29 4945,2470 5545,2470 5560,2455 v1(5629.03,2455) ; v1(5885,2465) 5990,2570 7002.48,2570 7210.35,2362.13 7482.13,2362.13 7506.75,2386.75 v1(7562.43,2386.75)
  Bottom Layer w10: v1(4660,2115) 4660,2415.88 v1(4680,2435.88) ; v1(5629.03,2455) 5639.03,2465 v1(5885,2465) ; v1(7562.43,2386.75) 7666.95,2282.22 7847.48,2282.22 J9.12@7900,2229.7
C2K_GPIO53: J1.109 J9.3 | length 4562.8
  Top Layer w10: J1.109@4607.48,1908.86 4607.48,2109.81 v1(4610,2112.33) ; v1(4630,2440.39) 4659.61,2470 4905,2470 4925,2490 v1(5595,2490) ; v1(5840,2500) 5869.32,2500 5964.32,2595 7009.56,2595 7224.56,2380 7452.68,2380 7570.15,2497.47 v1(8270,2497.47)
  Bottom Layer w10: v1(4610,2112.33) 4610,2122.57 4630,2142.57 v1(4630,2440.39) ; v1(5595,2490) 5830,2490 v1(5840,2500) ; v1(8270,2497.47) 8270,2359.7 J9.3@8300,2329.7
C2K_GPIO54: J1.100 J25.4 | length 3139.1
  Top Layer w10: J1.100@4764.96,1775 4764.96,1659.96 4720,1615 4720,1541.21 4786.21,1475 5075,1475 5090,1490 5401.49,1490 5570.9,1320.59 5879.41,1320.59 6317.04,882.96 6317.04,816.79 6868.83,265 6935,265 J25.4@7000,200
C2K_GPIO55: J1.102 J25.3 | length 3073.6
  Top Layer w10: J1.102@4733.46,1775 4733.46,1663.46 4695,1625 4695,1531 4775.75,1450.25 5086.58,1450.25 5106.33,1470 5386.49,1470 5556.49,1300 5870,1300 6292.29,877.71 6292.29,807.71 J25.3@6900,200
C2K_GPIO56: J1.104 J25.2 | length 3045.2
  Top Layer w10: J1.104@4701.97,1775 4701.97,1665.43 4670.47,1633.94 4670.47,1520.91 4764.79,1426.59 5100,1426.59 5123.41,1450 5373.03,1450 5543.03,1280 5860,1280 6268.63,871.37 6268.63,791.37 6800,260 J25.2@6800,200
C2K_GPIO57: J1.106 J25.1 | length 3015.4
  Top Layer w10: J1.106@4670.47,1775 4670.47,1666.96 4645,1641.49 4645,1515 4756.76,1403.24 5118.24,1403.24 5145,1430 5360,1430 5530,1260 5850,1260 6245.28,864.72 6245.28,779.72 6700,325 J25.1@6700,200
C2K_GPIO58: J1.108
C2K_GPIO59: J1.110
C2K_GPIO60: J13.10 J19.125 | length 2368.3
  Top Layer w10: J13.10@1579.98,2550 1629.98,2600 1790,2600 2260,2130 2740,2130 v1(2750,2120) ; J19.125@3560.01,1908.86 3560.01,2044.99 v1(3560,2047.69)
  Bottom Layer w10: v1(2750,2120) 2795.56,2074.44 3470.56,2074.44 3497.31,2047.69 v1(3560,2047.69)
